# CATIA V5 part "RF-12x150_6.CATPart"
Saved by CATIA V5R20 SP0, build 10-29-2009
Part number: _RF-12x150
Definition: NONE
Nomenclature: _RF-12x150
Source: Unknown
Description: PART-_RF-12x150-DESC
Bounding box of the stored display mesh (mm): x -150 to 24, y -6.9 to 6.9, z -6.9 to 6.9
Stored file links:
  C:\Users\Utente\Desktop\IO LAVORO\3D X SITO CF\X SITO\PLASTICA\RF\RF-12x150_6.CATPart
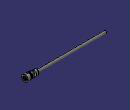
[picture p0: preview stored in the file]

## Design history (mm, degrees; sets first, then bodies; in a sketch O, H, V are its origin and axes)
Body1 "_RF-12x150" (main body)
  Solid1: solid without history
